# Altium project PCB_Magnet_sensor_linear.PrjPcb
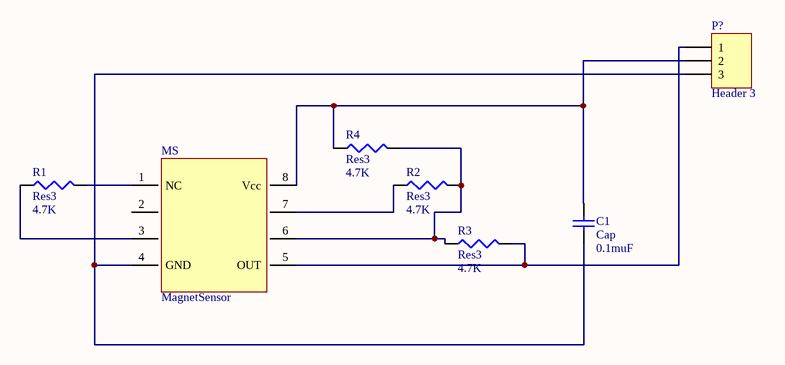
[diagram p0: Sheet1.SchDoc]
1 sheet, 7 parts. Net scope: global (net labels, ports and power ports of the same name join across sheets).
Board file: PCB1.PcbDoc

## Sheet Sheet1.SchDoc
size A

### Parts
C1  Cap  value 0.1muF  [CAPC3216M]
MS  MagnetSensor  [AD22151]
P1  Header 3  [HDR1X3]
R1  Res3  value 4.7K  [RESC3216M]
R2  Res3  value 4.7K  [RESC3216M]
R3  Res3  value 4.7K  [RESC3216M]
R4  Res3  value 4.7K  [RESC3216M]

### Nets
NetC1_1: C1.1 MS.4(GND) P1.3
NetC1_2: C1.2 MS.8(Vcc) P1.2 R4.1
NetMS_1: MS.1(NC) R1.2
NetMS_3: MS.3 R1.1
NetMS_5: MS.5(OUT) P1.1 R3.2
NetMS_6: MS.6 R2.2 R3.1 R4.2
NetMS_7: MS.7 R2.1

Not connected (* = marked no-connect by the designer): MS 2

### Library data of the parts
C1 = Cap: Capacitor
MS = Component_1
P1 = Header 3: Header, 3-Pin
R1-R4 = Res3: Resistor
